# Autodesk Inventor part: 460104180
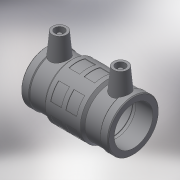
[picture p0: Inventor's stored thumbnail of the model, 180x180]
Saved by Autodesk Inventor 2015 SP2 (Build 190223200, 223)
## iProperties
Created: 2017-06
Part Number: 460104180
Material: Generic
Description: PLASSON LIGHTFIT COUPLER 180
Document SubType Name: Modeling
Designer: KIM
Mass: 89.5427 g
Surface Area: 304.58 cm^2
Volume: 89.5427 cm^3
Density: 1 g/cm^3
Appearance: Default
Author: KIM
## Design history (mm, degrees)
derived "460104.ipt"
feature "Solid1::460104.ipt"
tag "TaggingFeature1"
body "Solid1"
other parameters: "d13" = 212, "d14" = 17.6296, "d15" = 104, "d16" = 104, "d17" = 178.2, "d19" = 3.52592, "d20" = 168 deg, "d22" = 202.1, "d23" = 215, "d24" = 196.037, "d25" = 135 deg, "d26" = 84.8, "d27" = 135 deg, "d29" = 114, "d35" = 15, "d39" = 5 deg, "d44" = 4, "d46" = 14, "d47" = 0, "d52" = 210.7, "d53" = 10.6, "d54" = 10.6, "d55" = 10.6, "d56" = 35 deg, "d58" = 360 deg, "d60" = 20.8, "d61" = 135 deg, "d62" = 95.4, "d63" = 3, "d64" = 0, "L_" = 212, "L_1" = 104, "D_" = 215, "A_" = 114, "d_2" = 12
